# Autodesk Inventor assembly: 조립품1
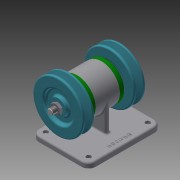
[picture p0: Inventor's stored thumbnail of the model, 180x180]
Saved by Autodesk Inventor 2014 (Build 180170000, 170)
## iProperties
Created: 2019-09
Part Number: 조립품1
Document SubType Name: Assembly
Designer: kh
Author: kh
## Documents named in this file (10)
- C:\Users\kh\Desktop\490904V1045\조립품1.iam
- C:\Users\kh\Desktop\490904V1045\V-벨트풀리.ipt
- C:\Users\kh\Desktop\490904V1045\너트 M10x1.ipt
- C:\Users\kh\Desktop\490904V1045\베어링 6004.ipt
- C:\Users\kh\Desktop\490904V1045\본체.ipt
- C:\Users\kh\Desktop\490904V1045\볼트 M4.ipt
- C:\Users\kh\Desktop\490904V1045\오일 실 17 30 5.ipt
- C:\Users\kh\Desktop\490904V1045\축.ipt
- C:\Users\kh\Desktop\490904V1045\커버.ipt
- C:\Users\kh\Desktop\490904V1045\키 5 x 5 x 12.ipt
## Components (2 placed, 1 different names)
1. V-벨트풀리:1
2. V-벨트풀리:2
